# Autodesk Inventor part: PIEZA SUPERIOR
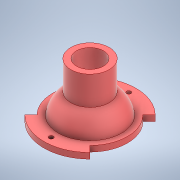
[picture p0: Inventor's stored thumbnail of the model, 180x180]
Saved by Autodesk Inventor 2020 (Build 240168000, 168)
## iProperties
Created: 2022-09
Part Number: PIEZA SUPERIOR
Material: Tuberías de PVC
Document SubType Name: Modeling
Designer: SEBAS
Density: 1.4 g/cm^3
Appearance: Suave - Rojo
Author: SEBAS
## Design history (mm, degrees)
sketch "Boceto1"
  geometry: L1 (0, 0)-(0, 14.523); L2 (-32, 0)-(-32, 4); L3 (-32, 4)-(-22, 4); L4 (-13.35, 17.938)-(-13.35, 37.938); L5 (-13.35, 37.938)-(-9.35, 37.938); L6 (-9.35, 37.938)-(-9.35, 0); L7 (-32, 0)-(-9.35, 0); A1 r 22.361 centre (0, 0) between (-13.35, 17.938) and (-22, 4)
  constraints: 14 end point, 4 perpendicular, 3 vertical, 2 point on circle, 1 centre point, 1 coincident, 1 horizontal, 1 horizontal alignment
  dimensions: "d0" = 32 distance of L1.start L2.start; "d1" = 4 distance of L2.start L2.end; "d2" = 26.7 diameter of L4 L1; "d3" = 10 distance of L2.end L3.end; "d4" = 20 vertical distance of L4.start L5.end
revolve "Revolución1" sketch "Boceto1" stored, may be unused: angle "d5" = 90 deg
sketch "Boceto2"
  geometry: L1 (32, 0)-(0, 0); L2 (0, 0)-(22.627, -22.627); L3 (0, 0)-(-22.627, 22.627); L4 (0, 0)-(-22.627, -22.627); L5 (0, 0)-(22.627, 22.627); L6 (0, 0)-(-32, 0); L7 (0, 32)-(0, 22); L8 (0, -32)-(0, -22); C1 r 32 at (0, 0) reference; C2 r 26 at (0, 0); C3 r 1.5 at (0, 27); C4 r 1.5 at (0, -27); A1 r 22 centre (0, 0) between (0, 22) and (0, -22) reference; 10 further points
  constraints: 16 end point, 3 centre point, 2 coincident, 2 horizontal, 2 midpoint, 2 point on circle, 2 point on line, 1 equal radius, 1 vertical, 1 vertical alignment, 11 other
  dimensions: "d6" = 52 diameter of C2; "d7" = 45 deg angle of L1 L2; "d8" = 45 deg angle of L6 L4; "d9" = 45 deg angle of L5 L1; "d10" = 45 deg angle of L6 L3; "d15" = 3 diameter of C3
extrude "Extrusión1" cut sketch "Boceto2" distance "d11" = 10; taper "d12" = 0 deg
extrude "Extrusión2" cut sketch "Boceto2" distance "d16" = 10; taper "d17" = 0 deg
node "Sólido1"
